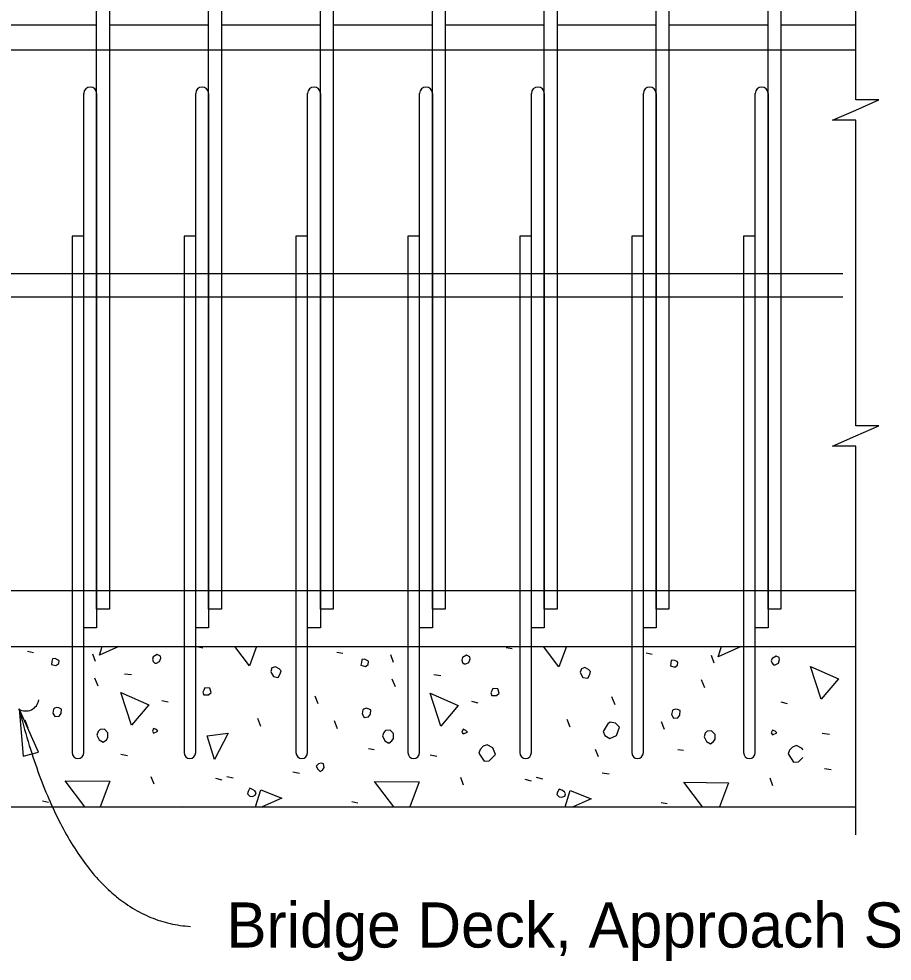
# Model space of a CAD drawing. Extents: x 120588.1 to 120659.6, y 120683.4 to 120715.5.
# Drawn here: x 120611.389 to 120615.29, y 120695.015 to 120699.225 of the extents above; entities that cross this region are included whole.
import ezdxf

# ---------------------------------------------------------------- set-up
doc = ezdxf.new("R2010")
doc.units = 0
for name, color, linetype in [('Dimension', 7, 'Continuous'), ('SheetBorder_dp', 7, 'Continuous'), ('SheetLines_dp', 7, 'Continuous'), ('SupstrConc', 7, 'Continuous')]:
    doc.layers.add(name, color=color, linetype=linetype)

msp = doc.modelspace()

# ---------------------------------------------------------------- linework, layer by layer
at = {"layer": 'Dimension'}
for p, q in [((120612.1835, 120696.4203), (120612.21, 120696.415)), ((120613.5659, 120696.4168), (120613.5924, 120696.4115)), ((120611.4269, 120696.3991), (120611.4534, 120696.3938)), ((120611.7309, 120696.3532), (120611.7186, 120696.3868)), ((120612.8093, 120696.3956), (120612.8358, 120696.3903)), ((120613.0625, 120696.3496), (120613.0501, 120696.3832)), ((120614.1917, 120696.3921), (120614.2182, 120696.3868)), ((120614.4957, 120696.3461), (120614.4834, 120696.3797)), ((120611.7423, 120696.2436), (120611.7281, 120696.2789)), ((120611.86, 120696.2984), (120611.8918, 120696.2948)), ((120613.0709, 120696.24), (120613.0568, 120696.2754)), ((120613.2424, 120696.2948), (120613.2742, 120696.2913)), ((120614.4533, 120696.2365), (120614.4392, 120696.2718)), ((120612.7262, 120696.164), (120612.712, 120696.1994)), ((120614.0523, 120696.1605), (120614.0382, 120696.1958)), ((120612.0279, 120696.1799), (120612.0562, 120696.1729)), ((120613.4103, 120696.1764), (120613.4386, 120696.1693)), ((120614.7927, 120696.1729), (120614.821, 120696.1658)), ((120611.4304, 120696.0562), (120611.4163, 120696.0915)), ((120612.4699, 120696.0633), (120612.4557, 120696.0986)), ((120612.8128, 120696.0526), (120612.7987, 120696.088)), ((120613.8523, 120696.0597), (120613.8381, 120696.0951)), ((120614.2736, 120696.0491), (120614.2595, 120696.0845)), ((120614.9783, 120696.0329), (120615.0101, 120696.0294)), ((120611.8441, 120695.9395), (120611.8741, 120695.9342)), ((120612.9507, 120695.9643), (120612.9754, 120695.9607)), ((120613.9778, 120695.9271), (120613.9654, 120695.9607)), ((120614.3331, 120695.9607), (120614.3578, 120695.9572)), ((120613.2265, 120695.936), (120613.2565, 120695.9307)), ((120612.6131, 120695.86), (120612.6431, 120695.8547)), ((120613.9954, 120695.8564), (120614.0255, 120695.8511)), ((120614.988, 120695.8762), (120615.018, 120695.8709)), ((120611.9926, 120695.8052), (120611.9802, 120695.8387)), ((120612.2666, 120695.8317), (120612.2949, 120695.8246)), ((120612.3178, 120695.8405), (120612.3461, 120695.8334)), ((120613.375, 120695.8016), (120613.3626, 120695.8352)), ((120613.649, 120695.8281), (120613.6772, 120695.8211)), ((120613.7002, 120695.837), (120613.7285, 120695.8299)), ((120614.7574, 120695.7981), (120614.745, 120695.8317)), ((120611.4941, 120695.7309), (120611.5206, 120695.7256)), ((120612.8765, 120695.7274), (120612.903, 120695.7221)), ((120612.1198, 120695.7062), (120612.1323, 120695.7037)), ((120614.2588, 120695.7238), (120614.2854, 120695.7185))]:
    msp.add_line(p, q, dxfattribs=at)
for points in [[(120611.7486, 120696.3814), (120611.7606, 120696.4203)], [(120611.8352, 120696.4203), (120611.7486, 120696.3814)], [(120612.4186, 120696.3337), (120612.3528, 120696.4203)], [(120612.451, 120696.4203), (120612.4186, 120696.3337)], [(120613.801, 120696.3302), (120613.7325, 120696.4203)], [(120613.8347, 120696.4203), (120613.801, 120696.3302)], [(120614.5134, 120696.3744), (120614.5275, 120696.4203)], [(120614.6157, 120696.4203), (120614.5134, 120696.3744)], [(120611.5347, 120696.3408), (120611.5542, 120696.3355), (120611.5665, 120696.3443), (120611.5683, 120696.3567), (120611.5648, 120696.3602), (120611.5506, 120696.3673), (120611.5383, 120696.3655), (120611.5365, 120696.3532), (120611.5347, 120696.3408)], [(120611.9961, 120696.3461), (120612.0032, 120696.3461), (120612.0173, 120696.3532), (120612.0226, 120696.3691), (120612.0209, 120696.3779), (120612.0067, 120696.385), (120611.989, 120696.3744), (120611.9855, 120696.3638), (120611.989, 120696.3532), (120611.9961, 120696.3461)], [(120612.9171, 120696.3373), (120612.9366, 120696.332), (120612.9489, 120696.3408), (120612.9507, 120696.3532), (120612.9472, 120696.3567), (120612.933, 120696.3638), (120612.9206, 120696.362), (120612.9189, 120696.3496), (120612.9171, 120696.3373)], [(120613.3785, 120696.3426), (120613.3856, 120696.3426), (120613.3997, 120696.3496), (120613.405, 120696.3655), (120613.4032, 120696.3744), (120613.3891, 120696.3814), (120613.3714, 120696.3708), (120613.3679, 120696.3602), (120613.3714, 120696.3496), (120613.3785, 120696.3426)], [(120614.2995, 120696.3337), (120614.3189, 120696.3284), (120614.3313, 120696.3373), (120614.3331, 120696.3496), (120614.3296, 120696.3532), (120614.3154, 120696.3602), (120614.303, 120696.3585), (120614.3013, 120696.3461), (120614.2995, 120696.3337)], [(120614.7609, 120696.339), (120614.768, 120696.339), (120614.7821, 120696.3461), (120614.7874, 120696.362), (120614.7856, 120696.3708), (120614.7715, 120696.3779), (120614.7538, 120696.3673), (120614.7503, 120696.3567), (120614.7538, 120696.3461), (120614.7609, 120696.339)], [(120612.5176, 120696.3019), (120612.5264, 120696.286), (120612.5476, 120696.2825), (120612.5565, 120696.2984), (120612.56, 120696.3125), (120612.5512, 120696.3213), (120612.5353, 120696.3302), (120612.5194, 120696.3249), (120612.5141, 120696.309), (120612.5176, 120696.3019)], [(120613.9, 120696.2984), (120613.9088, 120696.2825), (120613.93, 120696.2789), (120613.9389, 120696.2948), (120613.9424, 120696.309), (120613.9336, 120696.3178), (120613.9177, 120696.3266), (120613.9018, 120696.3213), (120613.8965, 120696.3054), (120613.9, 120696.2984)], [(120614.9728, 120696.1848), (120614.9251, 120696.3315), (120615.0506, 120696.2767), (120614.9728, 120696.1848)], [(120612.2153, 120696.2047), (120612.2365, 120696.2047), (120612.2471, 120696.2153), (120612.2418, 120696.2347), (120612.2188, 120696.2365), (120612.2153, 120696.2259), (120612.21, 120696.217), (120612.2153, 120696.2047), (120612.2118, 120696.2082)], [(120613.5019, 120696.2011), (120613.5232, 120696.2011), (120613.5338, 120696.2117), (120613.5285, 120696.2312), (120613.5055, 120696.233), (120613.5019, 120696.2224), (120613.4966, 120696.2135), (120613.5019, 120696.2011), (120613.4984, 120696.2047)], [(120611.8918, 120696.0686), (120611.8441, 120696.2153), (120611.9696, 120696.1605), (120611.8918, 120696.0686)], [(120613.2742, 120696.065), (120613.2265, 120696.2117), (120613.352, 120696.1569), (120613.2742, 120696.065)], [(120611.54, 120696.1234), (120611.5489, 120696.1074), (120611.5683, 120696.1092), (120611.5771, 120696.1216), (120611.5789, 120696.141), (120611.5665, 120696.1463), (120611.5577, 120696.1481), (120611.5471, 120696.1446), (120611.5436, 120696.141), (120611.54, 120696.1234)], [(120612.9224, 120696.1198), (120612.9313, 120696.1039), (120612.9507, 120696.1057), (120612.9595, 120696.1181), (120612.9613, 120696.1375), (120612.9489, 120696.1428), (120612.9401, 120696.1446), (120612.9295, 120696.141), (120612.9259, 120696.1375), (120612.9224, 120696.1198)], [(120614.3048, 120696.1163), (120614.3136, 120696.1004), (120614.3331, 120696.1021), (120614.3419, 120696.1145), (120614.3437, 120696.134), (120614.3313, 120696.1393), (120614.3225, 120696.141), (120614.3119, 120696.1375), (120614.3083, 120696.134), (120614.3048, 120696.1163)], [(120614.0061, 120696.0226), (120614.029, 120696.0102), (120614.0591, 120696.0226), (120614.0715, 120696.0597), (120614.0538, 120696.0774), (120614.0308, 120696.0827), (120614.0202, 120696.0756), (120614.0078, 120696.0562), (120613.999, 120696.0403), (120614.0061, 120696.0226)], [(120611.7373, 120696.0244), (120611.7479, 120696.0031), (120611.7656, 120695.9925), (120611.7797, 120696.0031), (120611.7868, 120696.0138), (120611.7868, 120696.035), (120611.7709, 120696.0509), (120611.7515, 120696.0491), (120611.7426, 120696.0403), (120611.7373, 120696.0244)], [(120611.9908, 120696.0332), (120612.0102, 120696.042), (120612.0032, 120696.0491), (120611.9908, 120696.0544), (120611.9855, 120696.042), (120611.9908, 120696.0332)], [(120612.263, 120695.9165), (120612.2294, 120696.0208), (120612.3231, 120696.0332), (120612.263, 120695.9165)], [(120613.0132, 120696.0208), (120613.0238, 120695.9996), (120613.0415, 120695.989), (120613.0557, 120695.9996), (120613.0627, 120696.0102), (120613.0627, 120696.0314), (120613.0468, 120696.0473), (120613.0274, 120696.0456), (120613.0185, 120696.0367), (120613.0132, 120696.0208)], [(120613.3732, 120696.0297), (120613.3926, 120696.0385), (120613.3856, 120696.0456), (120613.3732, 120696.0509), (120613.3679, 120696.0385), (120613.3732, 120696.0297)], [(120614.4498, 120696.0173), (120614.4604, 120695.9961), (120614.478, 120695.9855), (120614.4922, 120695.9961), (120614.4993, 120696.0067), (120614.4993, 120696.0279), (120614.4834, 120696.0438), (120614.4639, 120696.042), (120614.4551, 120696.0332), (120614.4498, 120696.0173)], [(120614.7556, 120696.0261), (120614.775, 120696.035), (120614.768, 120696.042), (120614.7556, 120696.0473), (120614.7503, 120696.035), (120614.7556, 120696.0261)], [(120613.4439, 120695.9448), (120613.4669, 120695.9077), (120613.4899, 120695.9095), (120613.4987, 120695.9183), (120613.5181, 120695.9377), (120613.5058, 120695.9678), (120613.481, 120695.9819), (120613.4633, 120695.9749), (120613.4492, 120695.9607), (120613.4439, 120695.9448)], [(120614.8912, 120695.9568), (120614.8882, 120695.9643), (120614.8634, 120695.9784), (120614.8457, 120695.9713), (120614.8316, 120695.9572), (120614.8263, 120695.9413)], [(120614.8263, 120695.9413), (120614.8493, 120695.9042), (120614.8723, 120695.9059), (120614.8811, 120695.9148), (120614.8912, 120695.9249)], [(120612.7244, 120695.8723), (120612.735, 120695.8617), (120612.7456, 120695.8688), (120612.7527, 120695.8794), (120612.7492, 120695.8971), (120612.7403, 120695.8988), (120612.728, 120695.8971), (120612.7174, 120695.8865), (120612.7244, 120695.8723)], [(120611.684, 120695.7037), (120611.5948, 120695.8211), (120611.7946, 120695.8193), (120611.7514, 120695.7037)], [(120613.0637, 120695.7037), (120612.9772, 120695.8175), (120613.177, 120695.8158), (120613.1351, 120695.7037)], [(120614.4435, 120695.7037), (120614.3596, 120695.814), (120614.5594, 120695.8122), (120614.5188, 120695.7037)], [(120612.4204, 120695.7521), (120612.4327, 120695.7504), (120612.4451, 120695.7557), (120612.4487, 120695.7663), (120612.4433, 120695.7751), (120612.4327, 120695.7822), (120612.4204, 120695.7875), (120612.4133, 120695.7733), (120612.4098, 120695.7627), (120612.4204, 120695.7521)], [(120612.4463, 120695.7037), (120612.4699, 120695.7804), (120612.5636, 120695.7433), (120612.4754, 120695.7037)], [(120613.8028, 120695.7486), (120613.8151, 120695.7468), (120613.8275, 120695.7521), (120613.831, 120695.7627), (120613.8257, 120695.7716), (120613.8151, 120695.7786), (120613.8028, 120695.7839), (120613.7957, 120695.7698), (120613.7922, 120695.7592), (120613.8028, 120695.7486)], [(120613.8297, 120695.7037), (120613.8523, 120695.7769), (120613.9459, 120695.7397), (120613.8657, 120695.7037)]]:
    msp.add_lwpolyline(points, dxfattribs=at)
at = {"layer": 'SheetBorder_dp'}
for p, q in [((120608.952, 120699.087), (120615.1275, 120699.087)), ((120608.952, 120698.0869), (120615.0702, 120698.0869)), ((120608.952, 120697.9828), (120615.0702, 120697.9828)), ((120608.952, 120696.6703), (120615.1275, 120696.6703)), ((120608.952, 120696.4203), (120615.1275, 120696.4203)), ((120608.952, 120695.7037), (120615.1275, 120695.7037))]:
    msp.add_line(p, q, dxfattribs=at)
at = {"layer": 'SheetLines_dp'}
for points in [[(120615.1275, 120697.6639), (120615.1275, 120698.7724), (120615.0241, 120698.7724), (120615.1275, 120698.8174), (120615.2308, 120698.8624), (120615.1275, 120698.8624), (120615.1275, 120701.1964)], [(120615.1274, 120695.5791), (120615.1274, 120697.3162), (120615.0241, 120697.3162), (120615.1274, 120697.3612), (120615.2308, 120697.4062), (120615.1274, 120697.4062), (120615.1274, 120697.6639)]]:
    msp.add_lwpolyline(points, dxfattribs=at)
msp.add_lwpolyline([(120611.3898, 120696.1414), (120611.4084, 120695.931), (120611.4767, 120695.9489)], close=True, dxfattribs=at)
msp.add_arc((120611.4194, 120696.1921), 0.0596, 238.8499, 350.5771, dxfattribs=at)
msp.add_open_spline([(120611.3892, 120696.1413), (120611.6285, 120695.2055), (120612.1553, 120695.1698)], degree=2, dxfattribs=at)
at = {"layer": 'SupstrConc'}
for p, q in [((120611.736, 120699.1964), (120611.2933, 120699.1964)), ((120612.236, 120699.1964), (120611.7933, 120699.1964)), ((120612.736, 120699.1964), (120612.2933, 120699.1964)), ((120613.236, 120699.1964), (120612.7933, 120699.1964)), ((120613.736, 120699.1964), (120613.2933, 120699.1964)), ((120614.236, 120699.1964), (120613.7933, 120699.1964)), ((120614.736, 120699.1964), (120614.2933, 120699.1964)), ((120615.1275, 120699.1964), (120614.7933, 120699.1964)), ((120615.1275, 120699.1964), (120614.8382, 120699.1964)), ((120611.6788, 120696.5037), (120611.6788, 120698.8917)), ((120611.736, 120698.8917), (120611.736, 120696.5037)), ((120612.1788, 120696.5037), (120612.1788, 120698.8917)), ((120612.236, 120698.8917), (120612.236, 120696.5037)), ((120612.6788, 120696.5037), (120612.6788, 120698.8917)), ((120612.736, 120698.8917), (120612.736, 120696.5037)), ((120613.1788, 120696.5037), (120613.1788, 120698.8917)), ((120613.236, 120698.8917), (120613.236, 120696.5037)), ((120613.6788, 120696.5037), (120613.6788, 120698.8917)), ((120613.736, 120698.8917), (120613.736, 120696.5037)), ((120614.1788, 120696.5037), (120614.1788, 120698.8917)), ((120614.236, 120698.8917), (120614.236, 120696.5037)), ((120614.6788, 120696.5037), (120614.6788, 120698.8917)), ((120614.736, 120698.8917), (120614.736, 120696.5037)), ((120611.6788, 120698.2537), (120611.6267, 120698.2537)), ((120611.6267, 120698.2537), (120611.6267, 120695.9464)), ((120611.6788, 120695.9464), (120611.6788, 120698.2537)), ((120612.1788, 120698.2537), (120612.1267, 120698.2537)), ((120612.1267, 120698.2537), (120612.1267, 120695.9464)), ((120612.1788, 120695.9464), (120612.1788, 120698.2537)), ((120612.6788, 120698.2537), (120612.6267, 120698.2537)), ((120612.6267, 120698.2537), (120612.6267, 120695.9464)), ((120612.6788, 120695.9464), (120612.6788, 120698.2537)), ((120613.1788, 120698.2537), (120613.1267, 120698.2537)), ((120613.1267, 120698.2537), (120613.1267, 120695.9464)), ((120613.1788, 120695.9464), (120613.1788, 120698.2537)), ((120613.6788, 120698.2537), (120613.6267, 120698.2537)), ((120613.6267, 120698.2537), (120613.6267, 120695.9464)), ((120613.6788, 120695.9464), (120613.6788, 120698.2537)), ((120614.1788, 120698.2537), (120614.1267, 120698.2537)), ((120614.1267, 120698.2537), (120614.1267, 120695.9464)), ((120614.1788, 120695.9464), (120614.1788, 120698.2537)), ((120614.6788, 120698.2537), (120614.6267, 120698.2537)), ((120614.6267, 120698.2537), (120614.6267, 120695.9464)), ((120614.6788, 120695.9464), (120614.6788, 120698.2537)), ((120611.736, 120696.5037), (120611.6788, 120696.5037)), ((120612.236, 120696.5037), (120612.1788, 120696.5037)), ((120612.736, 120696.5037), (120612.6788, 120696.5037)), ((120613.236, 120696.5037), (120613.1788, 120696.5037)), ((120613.736, 120696.5037), (120613.6788, 120696.5037)), ((120614.236, 120696.5037), (120614.1788, 120696.5037)), ((120614.736, 120696.5037), (120614.6788, 120696.5037))]:
    msp.add_line(p, q, dxfattribs=at)
for points in [[(120611.736, 120704.086), (120611.7933, 120704.086), (120611.7933, 120696.587), (120611.736, 120696.587)], [(120612.236, 120704.0235), (120612.2933, 120704.0235), (120612.2933, 120696.587), (120612.236, 120696.587)], [(120612.736, 120703.961), (120612.7933, 120703.961), (120612.7933, 120696.587), (120612.736, 120696.587)], [(120613.236, 120703.8985), (120613.2933, 120703.8985), (120613.2933, 120696.587), (120613.236, 120696.587)], [(120613.736, 120703.836), (120613.7933, 120703.836), (120613.7933, 120696.587), (120613.736, 120696.587)], [(120614.236, 120703.7735), (120614.2933, 120703.7735), (120614.2933, 120696.587), (120614.236, 120696.587)], [(120614.736, 120703.711), (120614.7933, 120703.711), (120614.7933, 120696.587), (120614.736, 120696.587)]]:
    msp.add_lwpolyline(points, close=True, dxfattribs=at)
for centre, radius, start, end in [((120611.7074, 120698.8917), 0.0286, 0, 180), ((120612.2074, 120698.8917), 0.0286, 0, 180), ((120612.7074, 120698.8917), 0.0286, 0, 180), ((120613.2074, 120698.8917), 0.0286, 0, 180), ((120613.7074, 120698.8917), 0.0286, 0, 180), ((120614.2074, 120698.8917), 0.0286, 0, 180), ((120614.7074, 120698.8917), 0.0286, 0, 180), ((120611.6527, 120695.9464), 0.026, 180, 0), ((120612.1527, 120695.9464), 0.026, 180, 0), ((120612.6527, 120695.9464), 0.026, 180, 0), ((120613.1527, 120695.9464), 0.026, 180, 0), ((120613.6527, 120695.9464), 0.026, 180, 0), ((120614.1527, 120695.9464), 0.026, 180, 0), ((120614.6527, 120695.9464), 0.026, 180, 0)]:
    msp.add_arc(centre, radius, start, end, dxfattribs=at)

# ---------------------------------------------------------------- texts
at = {"layer": 'SheetLines_dp'}
msp.add_text('Bridge Deck, Approach Slab or ', height=0.2016, dxfattribs=at).set_placement((120612.3155, 120695.0756))

doc.saveas('drawing.dxf')
